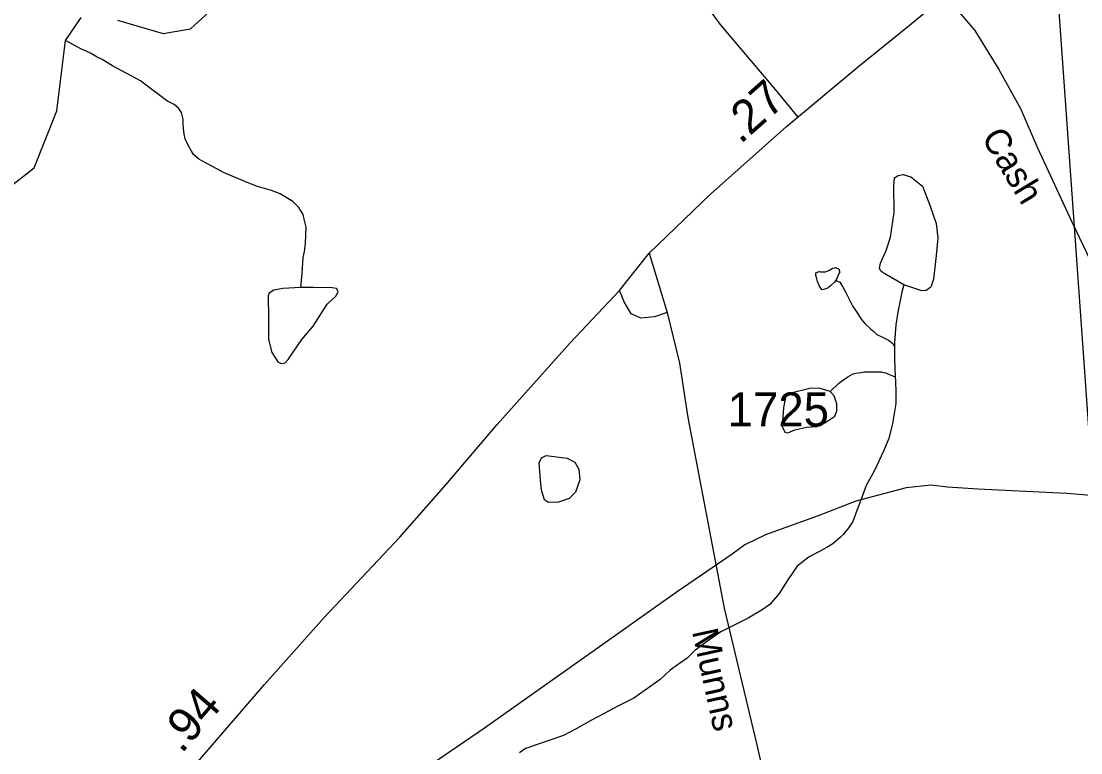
# Model space of a CAD drawing. Extents: x 2056842 to 2160602, y 826753 to 1016856.
# Drawn here: x 2075723 to 2079610, y 852470 to 855154 of the extents above; entities that cross this region are included whole.
import ezdxf

# ---------------------------------------------------------------- set-up
doc = ezdxf.new("R2010")
doc.units = 0
for name, color, linetype in [('Exist Hydrographic Creek Single Shore', 7, 'Continuous'), ('Exist Hydrographic Misc Water Feature', 7, 'Continuous'), ('Exist Railroad Mainline', 7, 'Continuous'), ('Exist Road Non-System Type 51', 7, 'Continuous'), ('Exist Road Primary US Attributed', 7, 'Continuous'), ('Exist Road Primary US Mileage Hundredths English Label', 7, 'Continuous'), ('Exist Road Secondary Type 51 Attributed', 7, 'Continuous'), ('Exist Road Secondary Type 51 Label', 7, 'Continuous'), ('Exist Road Secondary Type 51 Number Label', 7, 'Continuous'), ('Exist Utilities Electrical Transmission Line', 7, 'Continuous')]:
    doc.layers.add(name, color=color, linetype=linetype)

msp = doc.modelspace()

# ---------------------------------------------------------------- linework, layer by layer
at = {"layer": 'Exist Hydrographic Creek Single Shore'}
for points in [[(2075355.4, 854132.7), (2075513.3, 854165.6), (2075579.4, 854341.4), (2075629.4, 854507.7), (2075770.5, 854616.4), (2075853.3, 854824.7), (2075885.3, 855083.2), (2075943.3, 855167.4)], [(2076076.4, 855158), (2076243.3, 855108.7), (2076343.4, 855126.3), (2076426.4, 855200.1)], [(2078929.2, 853849.2), (2078931, 853833.1), (2078931.4, 853791.3), (2078931.4, 853751.1), (2078919.5, 853677.4), (2078905.8, 853623.1), (2078885.9, 853577), (2078853.9, 853505.2), (2078822.3, 853451.1), (2078804.3, 853400.7), (2078788.3, 853359), (2078774.5, 853318.8), (2078759, 853296.9), (2078738.9, 853270.7), (2078728.6, 853260.8), (2078700.9, 853236.7), (2078679, 853222.5), (2078651.1, 853208.5), (2078613.4, 853188.2), (2078569.5, 853154.4), (2078535.7, 853104.3), (2078503.5, 853054), (2078469.6, 853014.1), (2078441.5, 852994), (2078389.9, 852963.7), (2078334.1, 852935.6), (2078290, 852913.5), (2078232.4, 852873.1), (2078194, 852845.2), (2078166, 852817), (2078134.4, 852795.1), (2078104.2, 852772.9), (2078066.7, 852738.8), (2078032.7, 852714.8), (2077970.7, 852670.5), (2077908.8, 852640.2), (2077861, 852614.1), (2077815.1, 852589.9), (2077759.1, 852557.8), (2077713, 852533.6), (2077673.2, 852519.3), (2077605.3, 852497.1), (2077585.5, 852489.2), (2077573.1, 852485.4), (2077551.4, 852469.2)]]:
    msp.add_lwpolyline(points, dxfattribs=at)
at = {"layer": 'Exist Hydrographic Misc Water Feature'}
for points in [[(2076748.3, 854176.9), (2076753.5, 854229.7), (2076757.7, 854286.4), (2076761.8, 854308.5), (2076766.1, 854338.3), (2076767.5, 854370.5), (2076767.9, 854398.5), (2076761.3, 854428.2), (2076757.2, 854444.3), (2076741.7, 854470.2), (2076719.3, 854492.3), (2076673, 854520.4), (2076641, 854532.2), (2076589.3, 854547.7), (2076551.2, 854561.6), (2076497, 854585.6), (2076465.3, 854599.4), (2076426.9, 854619.4), (2076400.9, 854633.5), (2076374.6, 854647.2), (2076354.7, 854665.2), (2076346.7, 854679), (2076334.8, 854699.1), (2076324.8, 854722.9), (2076320.7, 854739), (2076318.2, 854760.8), (2076316.8, 854776.9), (2076316.4, 854794.8), (2076310.6, 854818.8), (2076300, 854835), (2076284.2, 854848.8), (2076262.5, 854859), (2076256.3, 854862.8), (2076191.9, 854910.6), (2076159.9, 854934.6), (2076057.8, 854990.2), (2076019.7, 855013.8), (2076001.8, 855021.8), (2075979.5, 855035.8), (2075961.6, 855043.7), (2075943.6, 855051.8), (2075885.3, 855083.2)], [(2078960.7, 854187), (2078891, 854227.2), (2078876.5, 854236.4), (2078871.2, 854248.3), (2078875.2, 854266.7), (2078896.3, 854312.9), (2078912.1, 854361.6), (2078925.2, 854452.6), (2078923.9, 854551.5), (2078926.6, 854579.1), (2078939.7, 854588.4), (2078958.2, 854591), (2078987.2, 854583.1), (2079029.3, 854548.8), (2079057, 854479), (2079079.4, 854411.7), (2079086, 854359), (2079079.4, 854294.4), (2079070.2, 854207.4), (2079059.6, 854178.4), (2079042.5, 854166.5), (2079026.7, 854165.2), (2078960.7, 854187)], [(2078711.6, 854204.4), (2078706.1, 854196.7), (2078695.8, 854186.5), (2078691.9, 854182.6), (2078684.1, 854176.5), (2078676.1, 854172.4), (2078669.8, 854170.5), (2078661.8, 854168.5), (2078656, 854174.3), (2078650.1, 854184.5), (2078643.9, 854198.4), (2078641.7, 854208.5), (2078637.8, 854220.4), (2078638, 854226.1), (2078637.8, 854230.2), (2078641.9, 854232.4), (2078646, 854234.2), (2078651.9, 854236.2), (2078655.8, 854234.4), (2078673.7, 854234.5), (2078680, 854236.4), (2078687.8, 854240.5), (2078694, 854244.4), (2078699.9, 854248.4), (2078705.9, 854248.7), (2078711.6, 854250.6), (2078715.5, 854248.4), (2078720, 854246.6), (2078723.9, 854242.7), (2078724.1, 854238.6), (2078726, 854234.7), (2078724.1, 854230.5), (2078721.9, 854224.7), (2078715.9, 854212.6), (2078714.1, 854208.5), (2078711.6, 854204.4)], [(2078711.6, 854204.4), (2078717.8, 854200.6), (2078726, 854196.5), (2078730.1, 854190.6), (2078736.2, 854180.8), (2078748.1, 854158.7), (2078764.1, 854126.7), (2078774.3, 854106.8), (2078788.5, 854086.8), (2078804.1, 854060.9), (2078818.4, 854045), (2078838.5, 854024.9), (2078850.4, 854015), (2078862.3, 854005), (2078882.4, 853995.1), (2078904.8, 853983.2), (2078920.5, 853971.1), (2078926.5, 853959.2)], [(2076748.3, 854176.9), (2076682.4, 854173), (2076649.5, 854167.7), (2076632.3, 854155.9), (2076628.4, 854146.6), (2076629.7, 854063.6), (2076629.7, 853985.8), (2076642.9, 853938.3), (2076663.9, 853904.1), (2076677.1, 853897.5), (2076691.6, 853900.1), (2076702.2, 853913.3), (2076752.2, 853985.8), (2076794.4, 854034.6), (2076845.8, 854116.3), (2076878.7, 854146.6), (2076885.3, 854162.4), (2076880, 854173), (2076864.2, 854175.6), (2076795.7, 854176.9), (2076748.3, 854176.9)], [(2078960.7, 854187), (2078954, 854159.5), (2078946.4, 854123.4), (2078940.4, 854093.4), (2078932.2, 854039.5), (2078926.7, 853975.4), (2078926.5, 853959.2)], [(2078926.5, 853959.2), (2078926.5, 853915.4), (2078929.2, 853849.2)], [(2078690.7, 853794.8), (2078723.1, 853826.5), (2078739.1, 853838.7), (2078755.3, 853848.8), (2078773.1, 853858.7), (2078785.2, 853863), (2078805.1, 853864.8), (2078817, 853867.1), (2078833, 853867.1), (2078861.1, 853867.3), (2078877.3, 853866.9), (2078886.7, 853865), (2078894.9, 853863.4), (2078905, 853859.4), (2078929.2, 853849.2)], [(2078690.7, 853794.8), (2078653.8, 853806.7), (2078620.9, 853808), (2078541.9, 853788.2), (2078527.4, 853773.7), (2078519.5, 853736.8), (2078514.2, 853666.9), (2078524.7, 853645.8), (2078535.3, 853643.2), (2078561.6, 853655.1), (2078603.8, 853664.3), (2078643.3, 853666.9), (2078671, 853680.1), (2078707.9, 853705.1), (2078715.8, 853723.6), (2078715.8, 853750), (2078705.2, 853779), (2078690.7, 853794.8)], [(2077627.9, 853471.7), (2077623.5, 853534), (2077631.5, 853551.8), (2077649.3, 853560.7), (2077725.7, 853550.9), (2077754.1, 853535.8), (2077768.3, 853510.9), (2077772.8, 853471.7), (2077756.8, 853426.4), (2077733.7, 853402.4), (2077694.6, 853389), (2077657.3, 853388.1), (2077643, 853397.9), (2077631.5, 853433.5), (2077627.9, 853471.7)]]:
    msp.add_lwpolyline(points, dxfattribs=at)
at = {"layer": 'Exist Railroad Mainline'}
msp.add_lwpolyline([(2079837.4, 853397.8), (2079559.3, 853421.3), (2079233.2, 853436.6), (2079121.2, 853444.3), (2079061.1, 853452.2), (2078969.1, 853442.1), (2078909.2, 853425.9), (2078785.1, 853393.6), (2078647.2, 853339.3), (2078453.3, 853268.9), (2078377.4, 853232.6), (2078331.5, 853198.6), (2078125.8, 853058.2), (2077794.3, 852823.4), (2077422.9, 852560.6), (2077129.3, 852359.9)], dxfattribs=at)
at = {"layer": 'Exist Road Non-System Type 51'}
for points in [[(2078151.5, 855329.4), (2078285.5, 855143.4), (2078495.2, 854896), (2078572.4, 854802)], [(2078092.8, 854084.8), (2078046.6, 854068.7), (2077996.7, 854064.5), (2077960.4, 854080.1), (2077935.4, 854124.8), (2077917.8, 854165.3)]]:
    msp.add_lwpolyline(points, dxfattribs=at)
at = {"layer": 'Exist Road Primary US Attributed'}
for points in [[(2078027.3, 854303), (2078252.2, 854519.7), (2078531, 854767.5), (2078796.3, 854988.4), (2078981.2, 855138), (2079112.9, 855248.1)], [(2074721.4, 850602.9), (2074899.4, 850780.9), (2075344.4, 851287.8), (2075732.3, 851722.7), (2076150.3, 852191.9), (2076286.3, 852339.4), (2076615, 852720.3), (2076834.1, 852966.6), (2077111.9, 853261.2), (2077281.2, 853452.4), (2077468.6, 853674.3), (2077737.6, 853974.6), (2077917.8, 854165.3), (2078027.3, 854303)]]:
    msp.add_lwpolyline(points, dxfattribs=at)
at = {"layer": 'Exist Road Secondary Type 51 Attributed'}
for points in [[(2079112.9, 855248.1), (2079221.6, 855119.8), (2079309.3, 854976.9), (2079389.3, 854833.5), (2079451.6, 854689.1), (2079577.8, 854418.4), (2079657.8, 854249), (2079822.4, 853997), (2080014.5, 853787), (2080233.1, 853607.8), (2080513.5, 853443.6), (2080723.7, 853353.7), (2081016.6, 853284.1), (2081253.4, 853264.3), (2081729.5, 853228.5), (2082003.7, 853206.7), (2082219.2, 853156.3), (2082405, 853066.9), (2082561.3, 852965.6), (2082612.5, 852919.6)], [(2078027.3, 854303), (2078092.8, 854084.8), (2078138.5, 853898.8), (2078168.1, 853699.8), (2078302, 853000.4), (2078420.4, 852503.6), (2078483.8, 852226.2), (2078525.3, 851935.2), (2078584.5, 851460.3), (2078592.8, 851289.9), (2078603.2, 851102.8), (2078565.8, 850849.2), (2078550.2, 850596.7), (2078552.3, 850355.6), (2078589.7, 850151.9), (2078642.6, 849961.8), (2078734, 849664.6), (2078798.4, 849394.4), (2078824.4, 849247.8), (2078828.5, 849110.7), (2078820.2, 848990.1), (2078779.7, 848824.9)]]:
    msp.add_lwpolyline(points, dxfattribs=at)
at = {"layer": 'Exist Utilities Electrical Transmission Line'}
msp.add_lwpolyline([(2079289.6, 845905.8), (2079948.4, 849305.4), (2079483.2, 855866.2), (2080101, 858353.8), (2081583.8, 864201.8), (2082616, 868304.1), (2080660.7, 871519), (2079505, 873046.5), (2077150, 875999.6), (2076168.7, 877076.1), (2079417.8, 882691.3), (2077477.1, 888146.6), (2075950.7, 892161.6), (2073748.3, 895216.6), (2070106.7, 900031.7)], dxfattribs=at)

# ---------------------------------------------------------------- texts
at = {"layer": 'Exist Road Primary US Mileage Hundredths English Label'}
for s, rotation, p in [('.27', 41.6333, (2078361.3, 854700.3)), ('.94', 49.2066, (2076311.2, 852463.9))]:
    msp.add_text(s, height=125, rotation=rotation, dxfattribs=at).set_placement(p)
at = {"layer": 'Exist Road Secondary Type 51 Label'}
for s, rotation, p in [('Cash', 301.1709, (2079243.5, 854727.4)), ('Munns', 282.3584, (2078183.5, 852915.3))]:
    msp.add_text(s, height=95, rotation=rotation, dxfattribs=at).set_placement(p)
at = {"layer": 'Exist Road Secondary Type 51 Number Label'}
msp.add_text('1725', height=125, dxfattribs=at).set_placement((2078314.7, 853667.2))

doc.saveas('drawing.dxf')
